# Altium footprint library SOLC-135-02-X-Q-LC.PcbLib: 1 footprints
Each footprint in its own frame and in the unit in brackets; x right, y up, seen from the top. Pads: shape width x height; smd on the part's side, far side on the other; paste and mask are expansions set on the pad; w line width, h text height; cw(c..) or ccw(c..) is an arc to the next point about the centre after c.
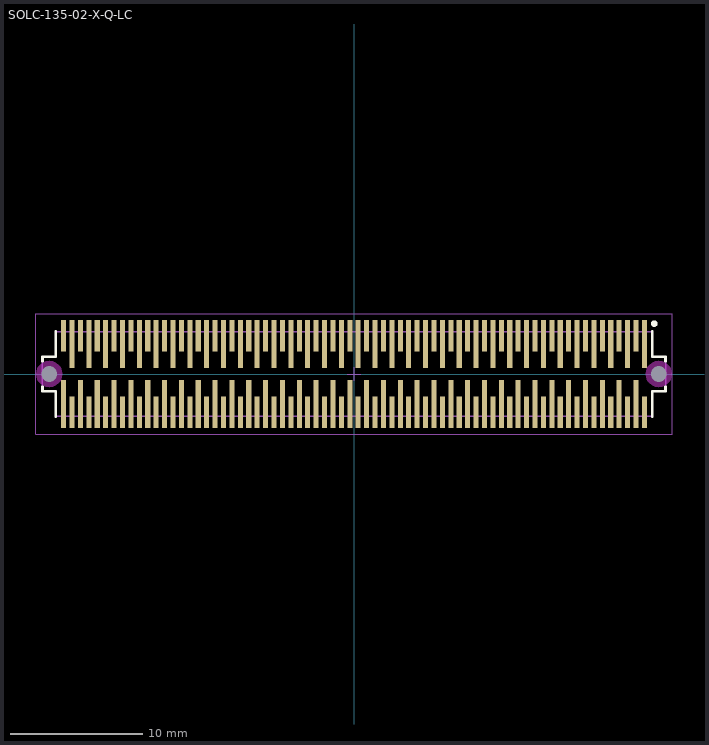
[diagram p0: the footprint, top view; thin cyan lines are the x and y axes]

## SOLC-135-02-X-Q-LC [mm] "1.27mm pitch, 140 pin, socket strip; 4 rows, w/locking clips, SMT"
height 4.62
pads (142):
  round 1 hole 1.2 unplated mask+0: 141(-22.987,0) 142(22.987,0)
  rect 0.38x2.36 smd mask+0: A1(21.273,2.885) A2(20.002,2.885) A3(18.732,2.885) A4(17.462,2.885) A5(16.192,2.885) A6(14.922,2.885) A7(13.652,2.885) A8(12.383,2.885) A9(11.112,2.885) A10(9.842,2.885) A11(8.572,2.885) A12(7.302,2.885) A13(6.032,2.885) A14(4.763,2.885) A15(3.492,2.885) A16(2.222,2.885) A17(0.953,2.885) A18(-0.318,2.885) A19(-1.587,2.885) A20(-2.857,2.885) A21(-4.127,2.885) A22(-5.397,2.885) A23(-6.667,2.885) A24(-7.938,2.885) A25(-9.207,2.885) A26(-10.477,2.885) A27(-11.747,2.885) A28(-13.018,2.885) A29(-14.287,2.885) A30(-15.557,2.885) A31(-16.828,2.885) A32(-18.098,2.885) A33(-19.367,2.885) A34(-20.637,2.885) A35(-21.907,2.885) D1(21.907,-2.885) D2(20.637,-2.885) D3(19.367,-2.885) D4(18.098,-2.885) D5(16.828,-2.885) D6(15.557,-2.885) D7(14.287,-2.885) D8(13.018,-2.885) D9(11.747,-2.885) D10(10.477,-2.885) D11(9.207,-2.885) D12(7.938,-2.885) D13(6.667,-2.885) D14(5.397,-2.885) D15(4.127,-2.885) D16(2.857,-2.885) D17(1.587,-2.885) D18(0.318,-2.885) D19(-0.953,-2.885) D20(-2.222,-2.885) D21(-3.492,-2.885) D22(-4.763,-2.885) D23(-6.032,-2.885) D24(-7.302,-2.885) D25(-8.572,-2.885) D26(-9.842,-2.885) D27(-11.112,-2.885) D28(-12.383,-2.885) D29(-13.652,-2.885) D30(-14.922,-2.885) D31(-16.192,-2.885) D32(-17.462,-2.885) D33(-18.732,-2.885) D34(-20.002,-2.885) D35(-21.273,-2.885)
  rect 0.38x3.63 smd mask+0: B1(21.907,2.25) B2(20.637,2.25) B3(19.367,2.25) B4(18.098,2.25) B5(16.828,2.25) B6(15.557,2.25) B7(14.287,2.25) B8(13.018,2.25) B9(11.747,2.25) B10(10.477,2.25) B11(9.207,2.25) B12(7.938,2.25) B13(6.667,2.25) B14(5.397,2.25) B15(4.127,2.25) B16(2.857,2.25) B17(1.587,2.25) B18(0.318,2.25) B19(-0.953,2.25) B20(-2.222,2.25) B21(-3.492,2.25) B22(-4.763,2.25) B23(-6.032,2.25) B24(-7.302,2.25) B25(-8.572,2.25) B26(-9.842,2.25) B27(-11.112,2.25) B28(-12.383,2.25) B29(-13.652,2.25) B30(-14.922,2.25) B31(-16.192,2.25) B32(-17.462,2.25) B33(-18.732,2.25) B34(-20.002,2.25) B35(-21.273,2.25) C1(21.273,-2.25) C2(20.002,-2.25) C3(18.732,-2.25) C4(17.462,-2.25) C5(16.192,-2.25) C6(14.922,-2.25) C7(13.652,-2.25) C8(12.383,-2.25) C9(11.112,-2.25) C10(9.842,-2.25) C11(8.572,-2.25) C12(7.302,-2.25) C13(6.032,-2.25) C14(4.763,-2.25) C15(3.492,-2.25) C16(2.222,-2.25) C17(0.953,-2.25) C18(-0.318,-2.25) C19(-1.587,-2.25) C20(-2.857,-2.25) C21(-4.127,-2.25) C22(-5.397,-2.25) C23(-6.667,-2.25) C24(-7.938,-2.25) C25(-9.207,-2.25) C26(-10.477,-2.25) C27(-11.747,-2.25) C28(-13.018,-2.25) C29(-14.287,-2.25) C30(-15.557,-2.25) C31(-16.828,-2.25) C32(-18.098,-2.25) C33(-19.367,-2.25) C34(-20.637,-2.25) C35(-21.907,-2.25)
Top Overlay:
  circle w0.25: c22.65,3.8 r0.125
  lines w0.2: -23.5,-0.95 -23.5,-1.3 -22.5,-1.3 -22.5,-3.2 ; -23.5,0.95 -23.5,1.3 -22.5,1.3 -22.5,3.2 ; 22.5,-3.2 22.5,-1.3 23.5,-1.3 23.5,-0.95 ; 22.5,3.2 22.5,1.3 23.5,1.3 23.5,0.95
Keep-Out Layer:
  pour cut-out: 23.97,0 23.937,0.255 23.839,0.492 23.682,0.695 23.479,0.852 23.242,0.95 22.987,0.983 22.732,0.95 22.495,0.852 22.292,0.695 22.135,0.492 22.037,0.255 22.004,0 22.037,-0.255 22.135,-0.492 22.292,-0.695 22.495,-0.852 22.732,-0.95 22.987,-0.983 23.242,-0.95 23.479,-0.852 23.682,-0.695 23.839,-0.492 23.937,-0.255
  pour cut-out: -22.004,0 -22.037,0.255 -22.135,0.492 -22.292,0.695 -22.495,0.852 -22.732,0.95 -22.987,0.983 -23.242,0.95 -23.479,0.852 -23.682,0.695 -23.839,0.492 -23.937,0.255 -23.97,0 -23.937,-0.255 -23.839,-0.492 -23.682,-0.695 -23.479,-0.852 -23.242,-0.95 -22.987,-0.983 -22.732,-0.95 -22.495,-0.852 -22.292,-0.695 -22.135,-0.492 -22.037,-0.255
Mechanical 12:
  lines w0.001: -23.5,-1.3 -23.5,1.3 -22.5,1.3 -22.5,3.2 22.5,3.2 22.5,1.3 23.5,1.3 23.5,-1.3 22.5,-1.3 22.5,-3.2 -22.5,-3.2 -22.5,-1.3 -23.5,-1.3
Mechanical 13:
  lines w0.1: -23.5,-1.3 -23.5,1.3 -22.5,1.3 -22.5,3.2 22.5,3.2 22.5,1.3 23.5,1.3 23.5,-1.3 22.5,-1.3 22.5,-3.2 -22.5,-3.2 -22.5,-1.3 -23.5,-1.3
  text ".Designator" at 0,-0.127 h1.52
Mechanical 15:
  lines w0.05: -0.5,0 0.5,0 ; 0,-0.5 0,0.5 ; -24,-4.55 -24,4.55 24,4.55 24,-4.55 -24,-4.55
